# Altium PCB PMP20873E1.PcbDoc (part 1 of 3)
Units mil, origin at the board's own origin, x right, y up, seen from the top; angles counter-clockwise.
Board outline 7700 x 3300 mil, 6 copper layers (Layer 1 - Top Layer, Layer 2 - Inner Signal 1, Layer 3 - Inner Signal 2, Layer 4 - Inner Signal 3, Layer 5 - Inner Signal 4, Layer 6 - Bottom Layer), stack 64 mil thick; 258 components, 121 nets, 676 pads, 168 vias.
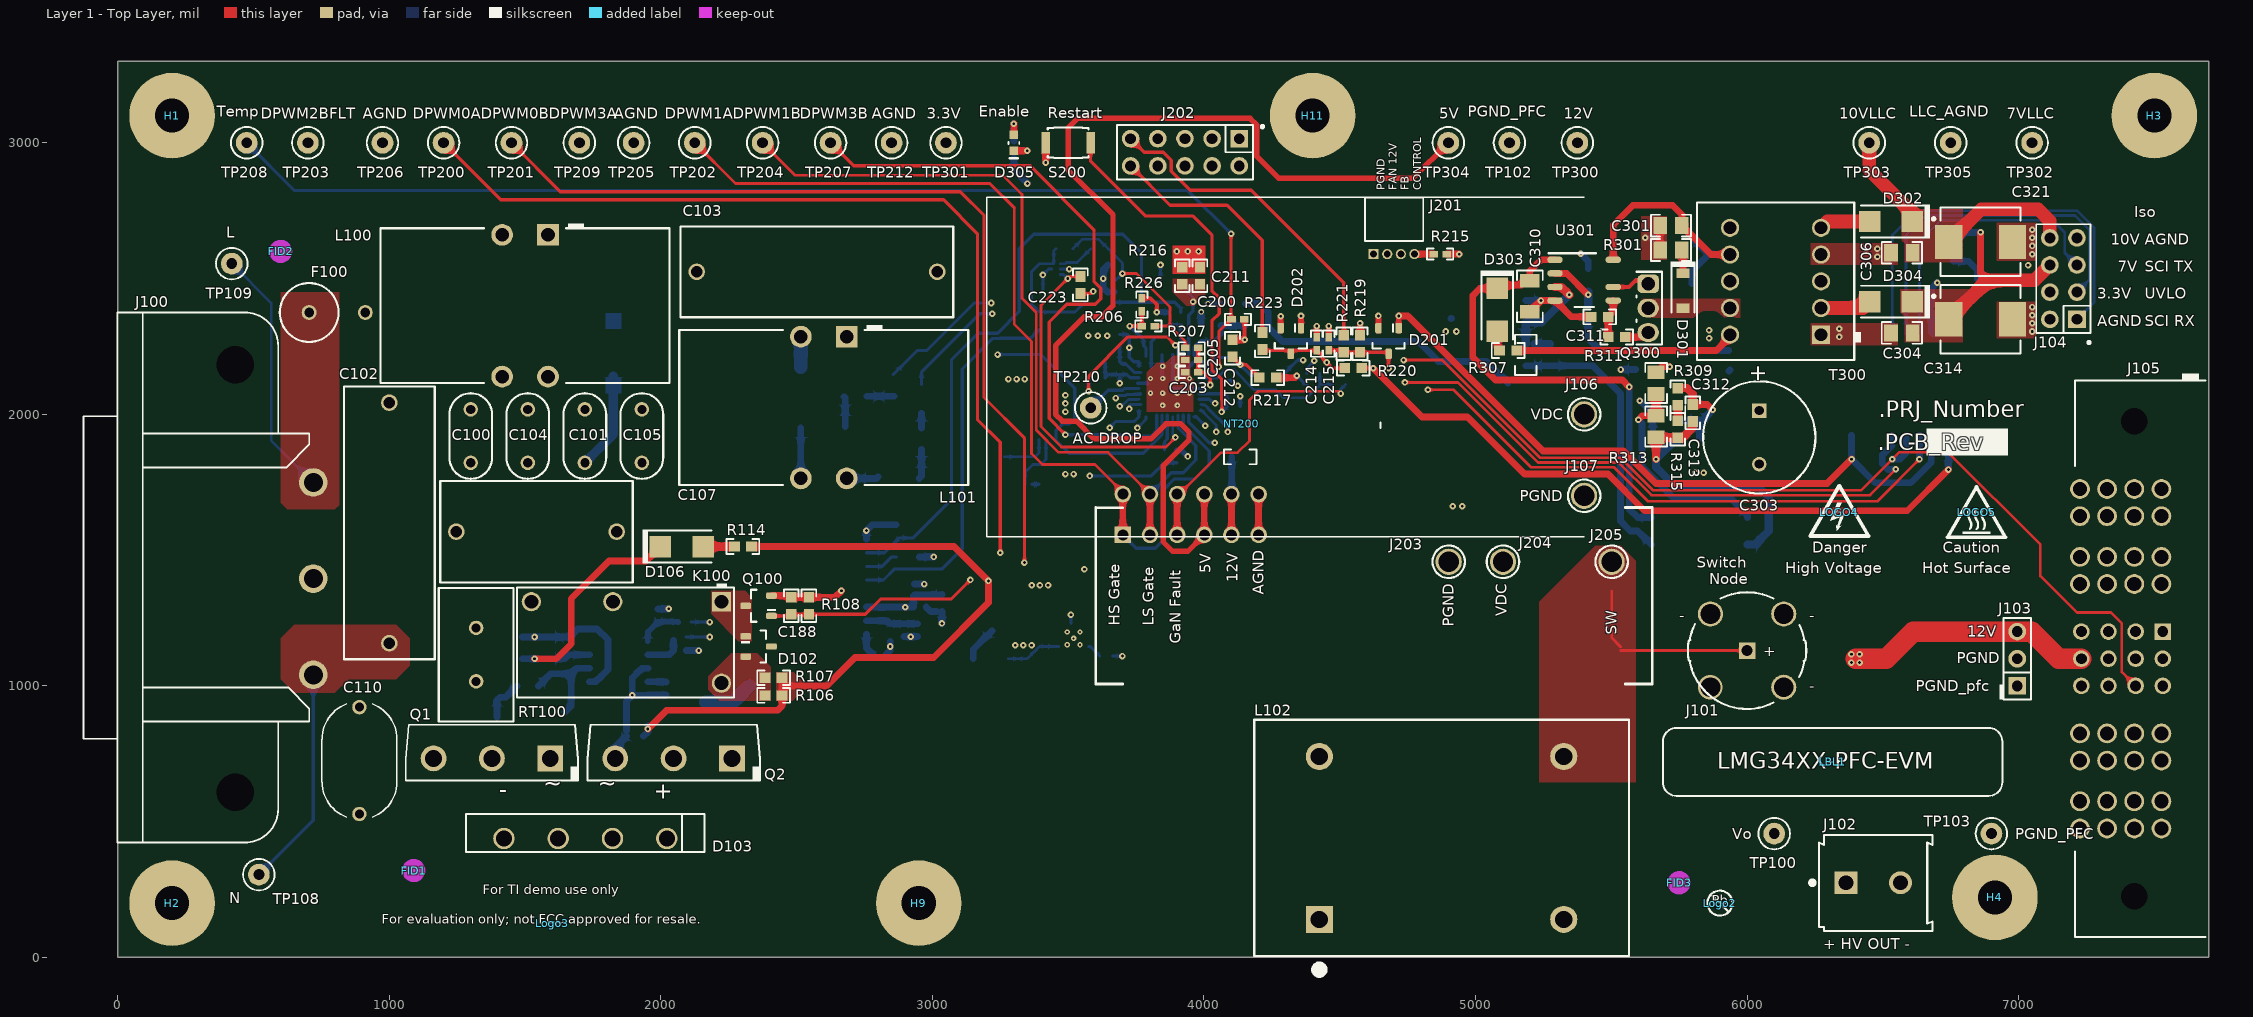
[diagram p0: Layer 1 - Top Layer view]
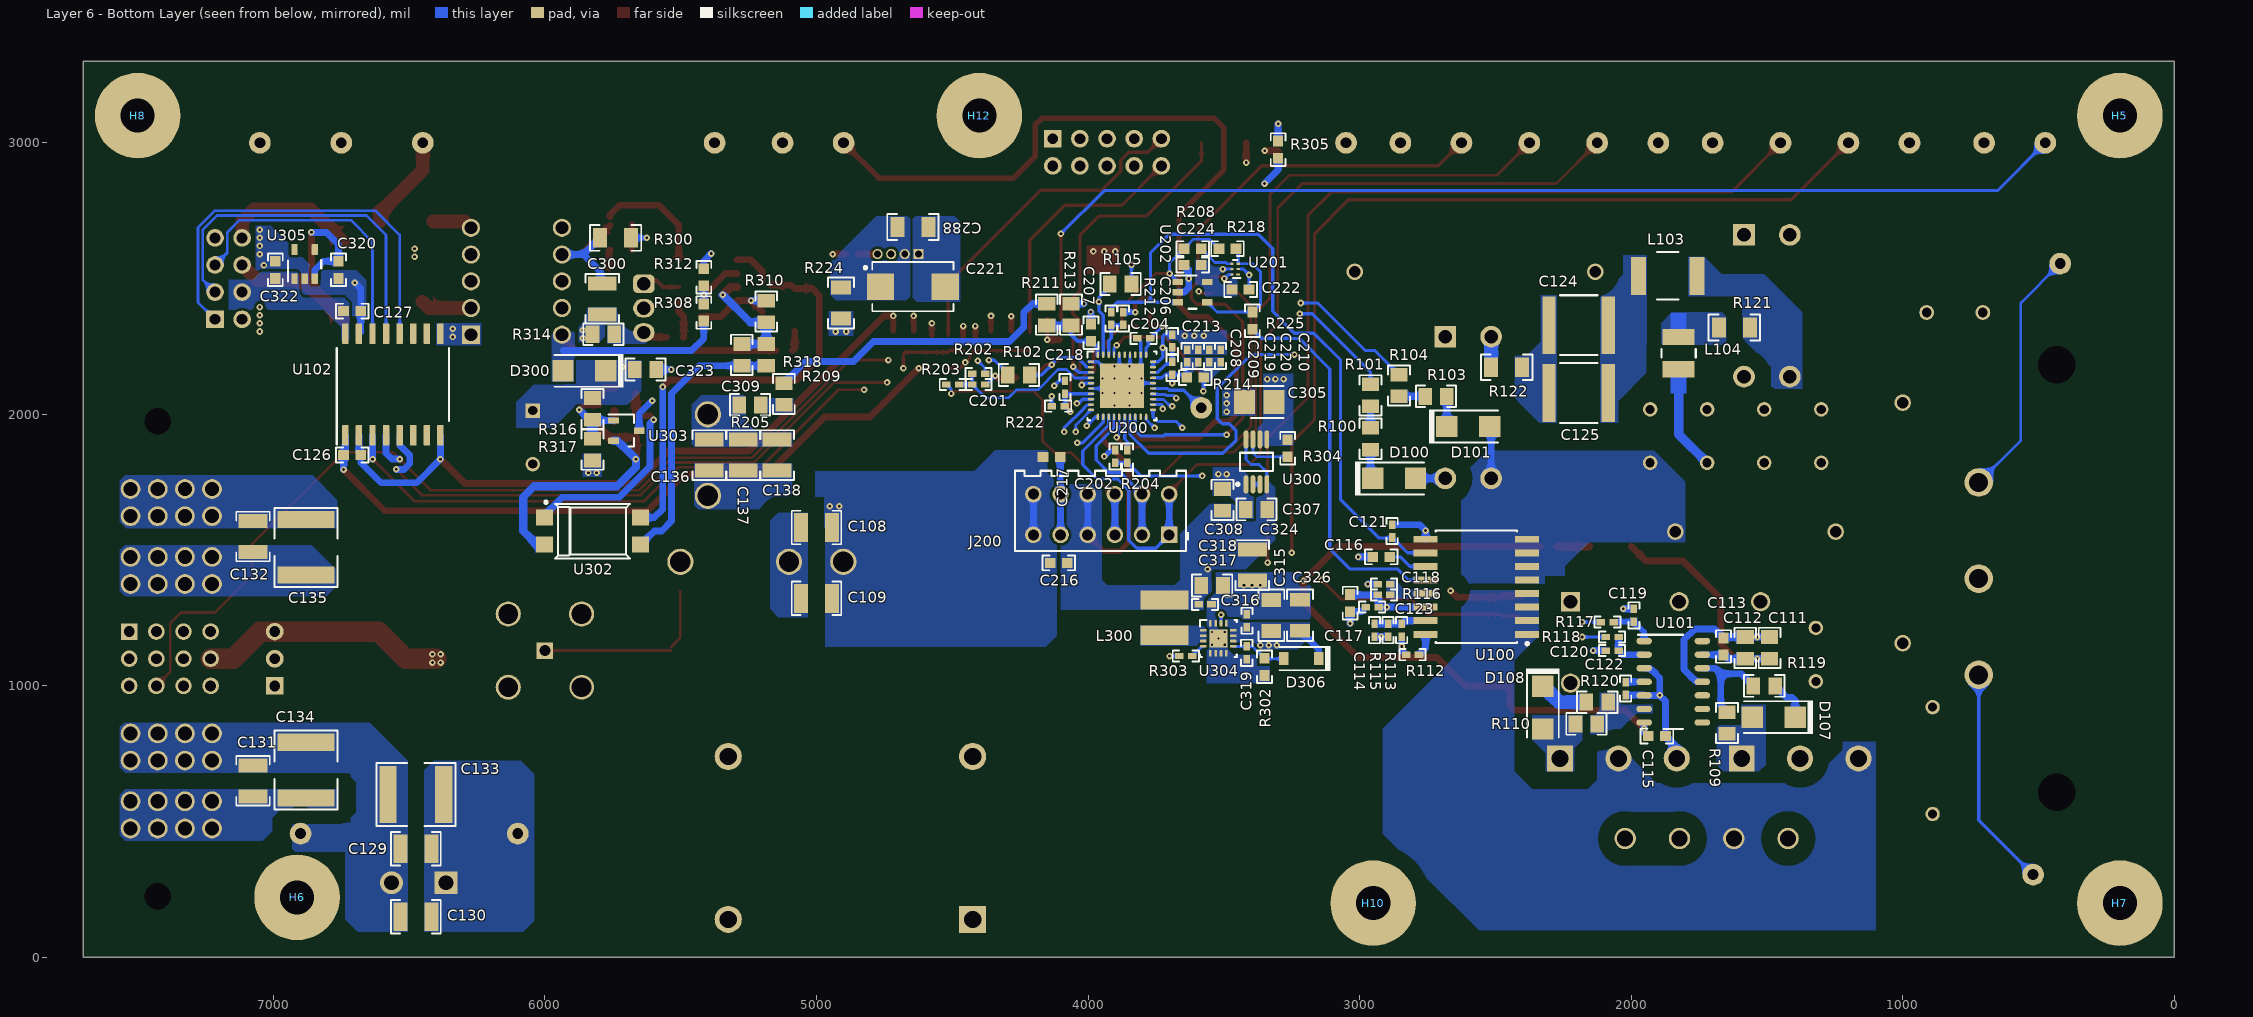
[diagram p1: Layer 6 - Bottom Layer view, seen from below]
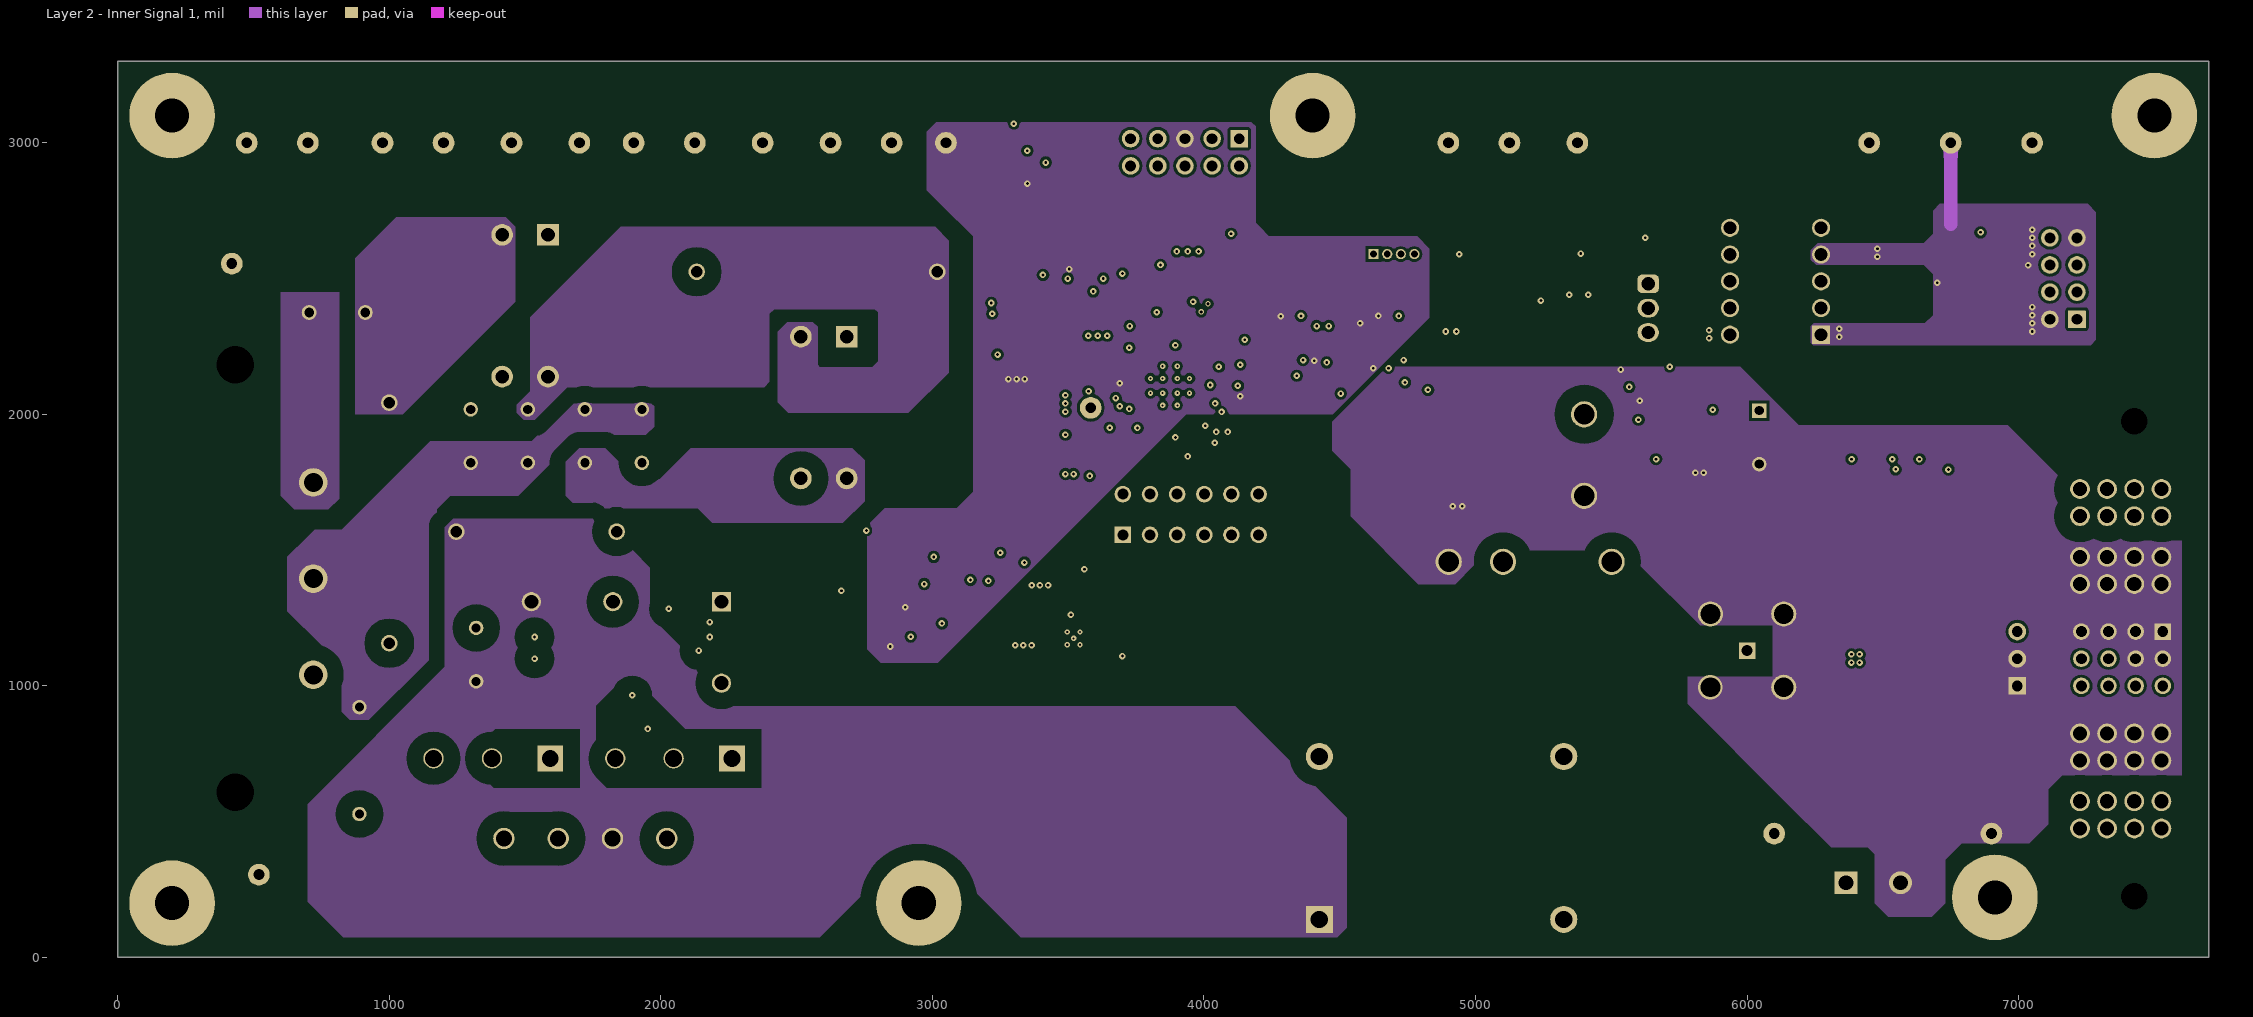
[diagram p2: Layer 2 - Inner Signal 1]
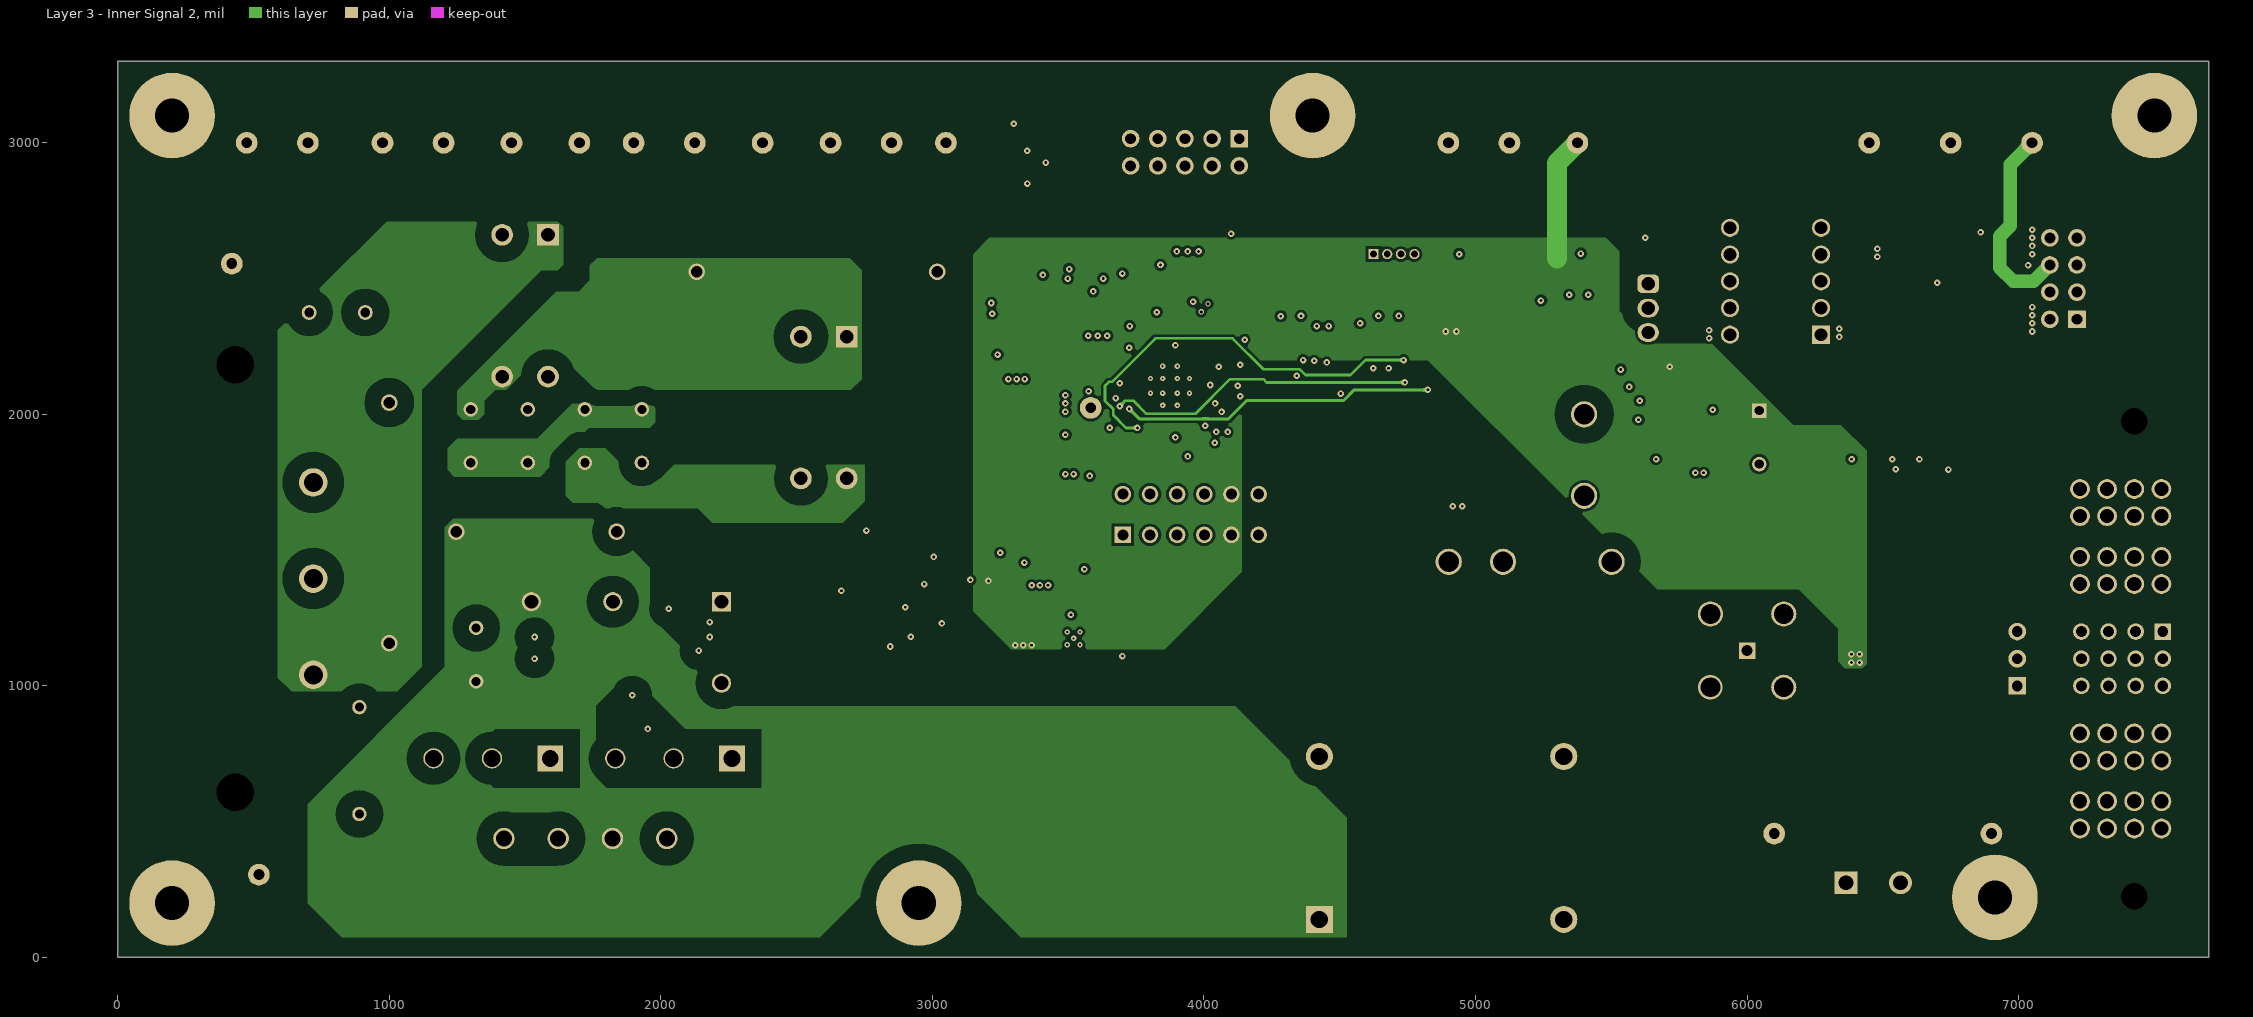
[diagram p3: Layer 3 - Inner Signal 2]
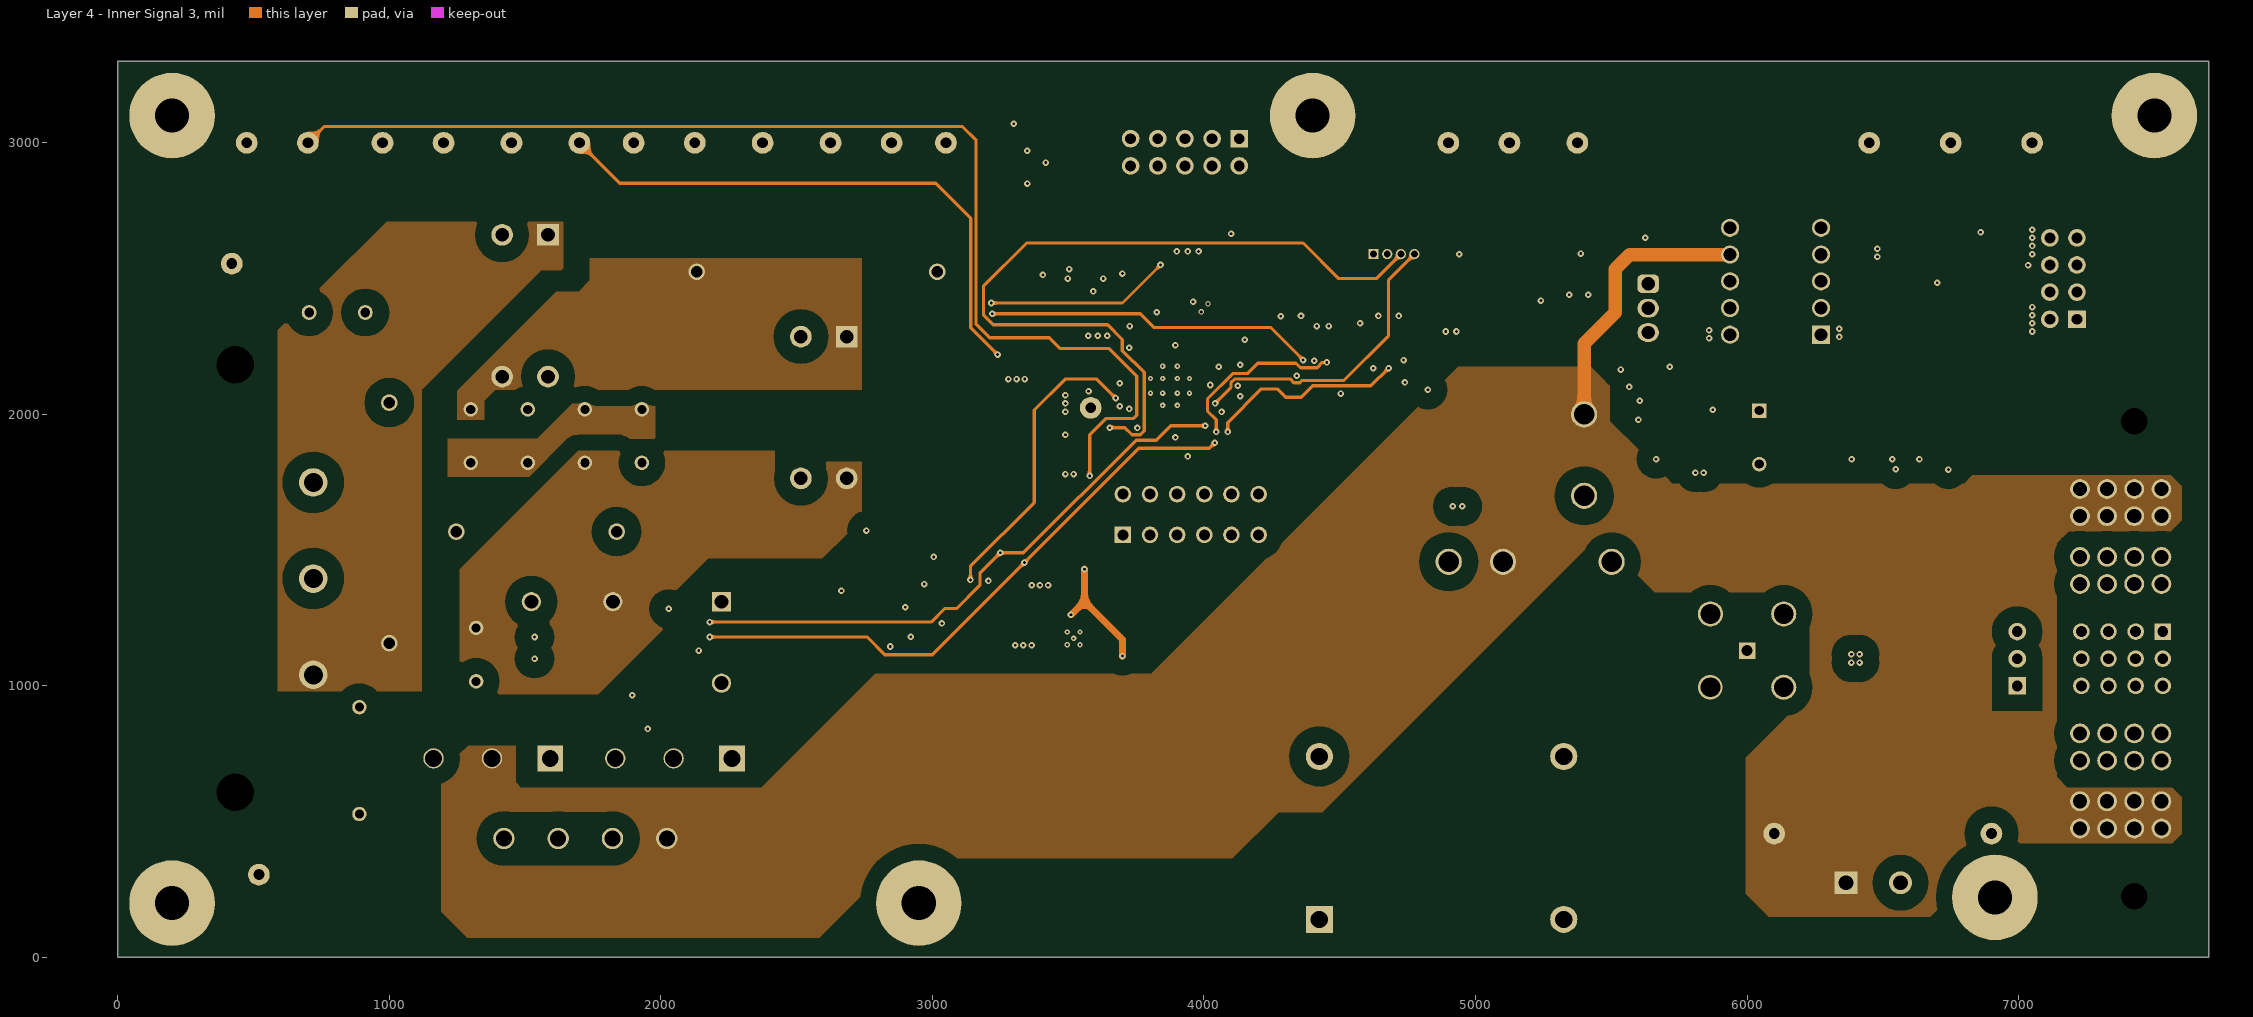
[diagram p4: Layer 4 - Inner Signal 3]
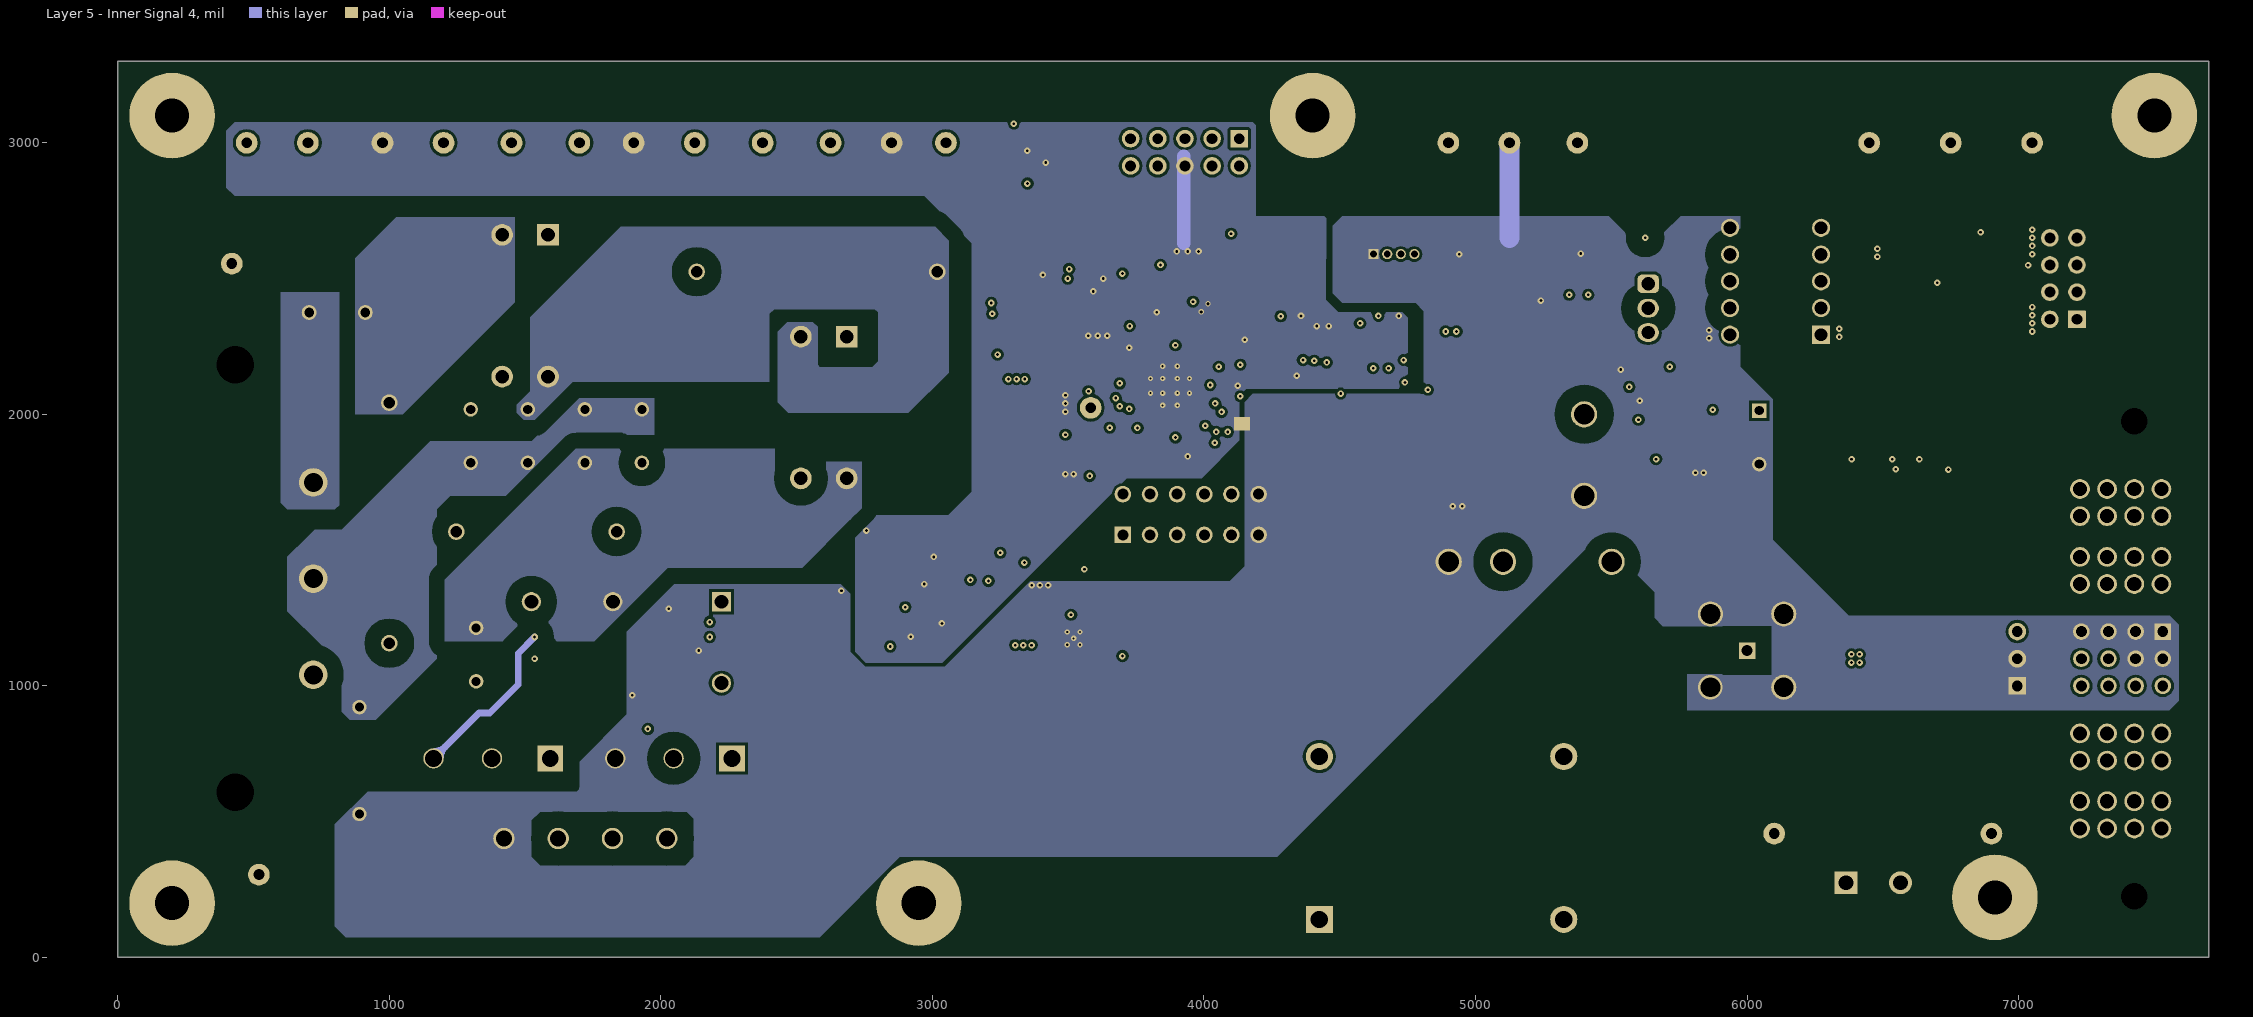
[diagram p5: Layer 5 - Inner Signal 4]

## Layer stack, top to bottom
Top Solder: solder mask 0.4, Solder Resist, Dk 3.5
Layer 1 - Top Layer: signal copper 1.4
Dielectric1: core 10, FR-4 High Tg, Dk 4.8
Layer 2 - Inner Signal 1: signal copper 2.8
Dielectric2: prepreg 10, FR-4 High Tg, Dk 4.8
Layer 3 - Inner Signal 2: signal copper 2.8
Dielectric3: core 10, FR-4 High Tg, Dk 4.8
Layer 4 - Inner Signal 3: signal copper 2.8
Dielectric4: prepreg 10, FR-4 High Tg, Dk 4.8
Layer 5 - Inner Signal 4: signal copper 2.8
Dielectric5: core 10, FR-4 High Tg, Dk 4.8
Layer 6 - Bottom Layer: signal copper 1.4
Bottom Solder: solder mask 0.4, Solder Resist, Dk 3.5

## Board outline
0,0 7700,0 7700,3300 0,3300

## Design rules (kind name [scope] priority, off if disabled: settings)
AcuteAngle [All] p1: minimum=4.50000000000000E+0001 checktracksonly=FALSE
AssemblyTestPointUsage [All] p1: valid=2
Clearance Clearance_5 [InComponent('L104') vs InComponent('L104')] p1: gap=59
Clearance Clearance_4 [InNetClass('VDC_HV') vs OnLayer('M1 Board Outline')] p2: gap=10
Clearance Clearance_SWNode_HV [InNetClass('SWNode') vs not InNetClass('SWNode')] p3: gap=60
Clearance Clearance_EARTH_HV [InNet('EARTH')] p4: gap=60
Clearance Clearance_3 [InNetClass('VAC_NEUTRAL') vs InNet('-BRDG_N')] p5: gap=24
Clearance Clearance_2 [InNetClass('VDC_HV') vs InComponent('Q300')] p6: gap=20
Clearance Clearance_1 [InNetClass('VDC_HV') vs InComponent('T300')] p7: gap=31
Clearance Clearance_VAC_NEUTRAL_HV [InNetClass('VAC_NEUTRAL') vs not InNetClass('VAC_NEUTRAL')] p8: gap=60
Clearance "Clearance_ VAC_LINE_HV" [InNetClass('VAC_LINE') vs not InNetClass('VAC_LINE')] p9: gap=60
Clearance "Clearance_ VAC_LINE_2_HV" [InNetClass('VAC_LINE_2') vs not InNetClass('VAC_LINE_2')] p10: gap=60
Clearance Clearance_SW_L_HV [InNetClass('SW_L') vs not InNetClass('SW_L')] p11: gap=60
Clearance Clearance_VDC_HV_HV [InNetClass('VDC_HV') vs not InNetClass('VDC_HV')and not InComponent('R205')] p12: gap=60
Clearance Clearance_BoardEdge_MountingHoles [OnCopper and InComponentClass('Mounting Holes') vs IsKeepOut] p13: gap=40
Clearance Clearance_BoardEdge_Poly [OnCopper and InPoly vs IsKeepOut] p14: gap=25
Clearance Clearance_BoardEdge [OnCopper and Not InComponentClass('Logo') and not InComponentClass('FiducialMark') and not InRegion(1000,500,4000,800) and Not IsKeepout vs IsKeepOut] p15: gap=75
Clearance Clearance_Poly [InPolygon] p16: gap=10
Clearance [All] p17: gap=7.5
ComponentClearance ComponentClearance_Shunt [InComponentClass('Header') vs InComponentClass('Shunt')] p1 off: gap=0 collisioncheckmode=3 verticalgap=0 showdistances=FALSE
ComponentClearance ComponentClearance_Logo [InComponentClass('Logo')] p2 off: gap=50 collisioncheckmode=3 verticalgap=10 showdistances=FALSE
ComponentClearance ComponentClearance_ScrewToNut [(HasFootprint('NY PMS 440 0025 PH')) vs (HasFootprint('Keystone_1902C'))] p3 off: gap=5 collisioncheckmode=3 verticalgap=10 showdistances=FALSE
ComponentClearance ComponentClearance_MountingHoles [InComponentClass('Mounting Holes')] p4 off: gap=250 collisioncheckmode=3 verticalgap=100000 showdistances=FALSE
ComponentClearance ComponentClearance_SmallPassives [HasFootprint('0201*') or HasFootprint('0402*') or HasFootprint('0508') or HasFootprint('0603*') or HasFootprint('0612') or HasFootprint('0805*') or HasFootprint('0815*') or HasFootprint('0830*') or HasFootprint('1206*') or HasFootprint('1210*') or HasFootprint('1808*') or HasFootprint('1812*') or HasFootprint('1825*') or HasFootprint('2010*') or HasFootprint('2220*') or HasFootprint('2225*') or HasFootprint('2512*') or HasFootprint('2728*') or HasFootprint('3518*') vs HasFootprint('0201*') or HasFootprint('0402*') or HasFootprint('0508') or HasFootprint('0603*') or HasFootprint('0612') or HasFootprint('0805*') or HasFootprint('0815*') or HasFootprint('0830*') or HasFootprint('1206*') or HasFootprint('1210*') or HasFootprint('1808*') or HasFootprint('1812*') or HasFootprint('1825*') or HasFootprint('2010*') or HasFootprint('2220*') or HasFootprint('2225*') or HasFootprint('2512*') or HasFootprint('2728*') or HasFootprint('3518*')] p5 off: gap=20 collisioncheckmode=3 verticalgap=10 showdistances=FALSE
ComponentClearance ComponentClearance_THtoSMT [IsThruComponent vs IsSMTComponent] p6 off: gap=100 collisioncheckmode=3 verticalgap=30 showdistances=FALSE
ComponentClearance ComponentClearance_THtoTH [IsThruComponent vs IsThruComponent] p7 off: gap=118.11 collisioncheckmode=3 verticalgap=30 showdistances=FALSE
ComponentClearance [All] p8 off: gap=40 collisioncheckmode=3 verticalgap=10 showdistances=FALSE
DiffPairsRouting [All] p1: maxlimit=100 minlimit=10 mostfreqgap=10 toplayer_minwidth=15 toplayer_maxwidth=15 toplayer_prefwidth=15 midlayer1_minwidth=15 midlayer1_maxwidth=15 midlayer1_prefwidth=15 midlayer2_minwidth=15 midlayer2_maxwidth=15 midlayer2_prefwidth=15 midlayer3_minwidth=15 midlayer3_maxwidth=15 midlayer3_prefwidth=15 midlayer4_minwidth=15 midlayer4_maxwidth=15 midlayer4_prefwidth=15 bottomlayer_minwidth=15 bottomlayer_maxwidth=15 bottomlayer_prefwidth=15 maxuncoupledlength=1000
FabricationTestPointUsage TestPointUsage [All] p1: valid=2 allowmultiple=FALSE
FabricationTestpoint Testpoint [All] p1: side=3 testpointundercomponent=TRUE minsize=40 maxsize=100 preferedsize=60 minholesize=0 maxholesize=40 preferedholesize=32 testpointgrid=1 allowsidetop=TRUE allowsidebottom=TRUE usegrid=TRUE gridtolerance=0.01
FanoutControl Fanout_LCC [IsLCC] p1: bgadir=Out bgaviamode=Centered fanoutstyle=Auto fanoutdirection=Alternating viagrid=1 // Fanout_LCC (Default Rule)
FanoutControl Fanout_BGA [IsBGA] p2: bgadir=Out bgaviamode=Centered fanoutstyle=Auto fanoutdirection=Alternating viagrid=1 // Fanout_BGA (Default Rule)
FanoutControl Fanout_Default [All] p4: bgadir=Out bgaviamode=Centered fanoutstyle=Auto fanoutdirection=Alternating viagrid=1 // Fanout_Default (Default Rule)
FanoutControl Fanout_Small [(CompPinCount < 5)] p5: bgadir=Out bgaviamode=Centered fanoutstyle=Auto fanoutdirection=OutThenIn viagrid=1 // Fanout_Small (Default Rule)
Height [All] p1: minheight=0 maxheight=2500 prefheight=500
HoleSize [All] p1: absolutevalues=TRUE maxlimit=251 minlimit=7.8 maxpercent=80.000 minpercent=20.000
MinimumAnnularRing MinimumAnnularRing_ThermalPadVias [IsVia and InAnyComponent] p1: minimumring=5.91
MinimumAnnularRing [All] p2: minimumring=3.5
MinimumSolderMaskSliver MinimumSolderMaskSliver_Logo [InComponentClass('Logo') vs InComponentClass('Logo')] p1: minsoldermaskwidth=0.7
MinimumSolderMaskSliver [All] p2: minsoldermaskwidth=0
PlaneConnect [All] p1: planeconnectstyle=Relief reliefexpansion=10 reliefentries=4 reliefconductorwidth=10 reliefairgap=10
PolygonConnect [All] p1: connectstyle=Direct reliefconductorwidth=10 reliefentries=4 polygonreliefangle="90 Angle" airgapwidth=10
RoutingVias ThermalPadVias [IsVia and InAnyComponent] p1: holewidth=7.87 width=19.68 viastyle="Through Hole" minholewidth=7.87 minwidth=19.68 maxholewidth=12.99 maxwidth=23.62
RoutingVias [All] p2: holewidth=12 width=20 viastyle="Through Hole" minholewidth=7.87 minwidth=15 maxholewidth=393.7 maxwidth=314.96
SMDToCorner [All] p1: distance=10000
SilkToSilkClearance [All] p1 off: silktosilkclearance=1
SilkToSolderMaskClearance SilkscreenOverComponentPads [IsPad] p1 off: minsilkscreentomaskgap=1 clearancetoexposedcopper=TRUE
SolderMaskExpansion [All] p1: expansion=1.97
Width [All] p1: maxlimit=100 minlimit=7 preferedwidth=10 checkconnectedcopper=TRUE
15 further rules are at their usual default settings.

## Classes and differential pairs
net class VAC_LINE_2: AC_L
net class LLC: 3V3LLC 7VLLC 10VLLC 12V LLC_AGND NetD302_2 NetD304_2 NetJ104_1 NetJ104_3 NetJ104_5 NetU102_10 NetU102_11 NetU305_4 PGND_PFC
net class VDC_HV: CT1 HVBUS NetC301_2 NetD301_1 NetD301_2
net class VAC_LINE: NetC100_1 NetC101_1 NetC102_1
component class SV601259E2_Power: C100 C101 C102 C103 C104 C105 C107 C108 C109 C110 C111 C112 C113 C114 C115 C116 C117 C118 C119 C120 C121 C122 C123 C124 C125 C126 C127 C129 C130 C131 C132 C133 C134 C135 C136 C137 C138 C188 D100 D101 D102 D103 D106 D107 D108 F100 J100 J101 J102 J103 J104 J105 J106 J107 K100 L100 L101 L102 L103 L104 Q1 Q2 Q100 R100 R101 R102 R103 R104 R105 R106 R107 R108 R109 R110 R112 R113 R114 R115 R116 R117 R118 R119 R120 R121 R122 RT100 TP100 TP102 TP103 TP108 TP109 U100 U101 U102
component class Header: J103 J104 J202
component class SV601259E2_Control: C200 C201 C202 C203 C204 C205 C206 C207 C208 C209 C210 C211 C212 C213 C214 C215 C216 C217 C218 C219 C220 C221 C222 C223 C224 C288 D201 D202 J200 J201 J202 J203 J204 J205 NT200 R202 R203 R204 R205 R206 R207 R208 R209 R211 R212 R213 R214 R215 R216 R217 R218 R219 R220 R221 R222 R223 R224 R225 R226 S200 TP200 TP201 TP202 TP203 TP204 TP205 TP206 TP207 TP208 TP209 TP210 TP212 U200 U201 U202
component class SV601259E2_Bias: C300 C301 C303 C304 C305 C306 C307 C308 C309 C310 C311 C312 C313 C314 C315 C316 C317 C318 C319 C320 C321 C322 C323 C324 C326 D300 D301 D302 D303 D304 D305 D306 L300 Q300 R300 R301 R302 R303 R304 R305 R307 R308 R309 R310 R311 R312 R313 R314 R315 R316 R317 R318 T300 TP300 TP301 TP302 TP303 TP304 TP305 U300 U301 U302 U303 U304 U305
component class "Mounting Holes": H1 H2 H3 H4 H9 H11
component class SV601259E2_Hardware: FID1 FID2 FID3 H1 H2 H3 H4 H5 H6 H7 H8 H9 H10 H11 H12 LBL1 Logo2 Logo3 LOGO4 LOGO5 ZZ1 ZZ2 ZZ3 ZZ4
component class FiducialMark: FID1 FID2 FID3
component class AssemblyNote: ZZ1 ZZ2 ZZ3 ZZ4
component class Label: LBL1
net class SW_L: +BRDG_N -BRDG_N NCD1 NCD2 NCD3 NCD4 NetC111_1 NetD107_1 NetD107_2
net class VAC_NEUTRAL: AC_N NetC102_2 NetC103_2
net class SWNode: SWNODE

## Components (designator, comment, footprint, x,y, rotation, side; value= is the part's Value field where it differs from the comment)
C100 "DE2E3KY222MA2BM01" CAPRD500W60D800H850 1300,1920 r270 top
C101 "DE2E3KY222MA2BM01" CAPRD500W60D800H850 1720,1920 r90 top
C102 "ECQ-U2A474ML" CAPRR2250W80L2550T850H1750 1000,1600 r270 top
C103 "R46KN-4100--P1 M" CAPRR2250W80L2550T850H1750 2575,2525 r0 top
C104 "DE2E3KY222MA2BM01" CAPRD500W60D800H850 1510,1920 r90 top
C105 "DE2E3KY222MA2BM01" CAPRD500W60D800H850 1930,1920 r270 top
C107 "450MPK105J" MPK_1800x950 1542,1568 r0 top
C108 "GRM32DR72J473KW01L" 1210 5000,1583.27 r180 bottom
C109 "GRM32DR72J473KW01L" 1210 5000,1322.05 r180 bottom
C110 "C921U222MYWDBA7317" CAPRD1000W60D900H1200 890,725 r270 top
C111 "0805YD106MAT2A" 0805_HV 1490,1140 r90 bottom
C112 "0805YD106MAT2A" 0805_HV 1580,1140 r90 bottom
C113 "C1608X7R1E105K080AB" 0603 1660,1145 r270 bottom
C114 "GRM155R70J104KA01D" 0402 2945,1205 r270 bottom
C115 "C0603X103K5RACTU" 0603 1905,815 r180 bottom
C116 "C1608X7R1H102K" 0603 2920,1475 r0 bottom
C117 "GRM185R60J105KE26D" 0603 3035,1305 r270 bottom
C118 "GRM155R70J223KA01D" 0402 2910,1375 r180 bottom
C119 "C1005X7R1H102K" 0402 1990,1260 r90 bottom
C120 "GRM155R60J102KA01D" 0402 2070,1130 r0 bottom
C121 "GRM155R60J102KA01D" 0402 2880,1570 r90 bottom
C122 "GRM155R70J104KA01D" 0402 2020,990 r270 bottom
C123 "GRM155R70J104KA01D" 0402 2953.62,1290 r0 bottom
C124 "GA355XR7GB563KW06L" 2220_330_N 2193.41,2328.41 r0 bottom
C125 "GA355XR7GB563KW06L" 2220_330_N 2193.41,2078.41 r0 bottom
C126 "C1608X7R1E105K080AB" 0603 6710,1850 r0 bottom
C127 "C1608X7R1E105K080AB" 0603 6710,2380 r0 bottom
C129 "GRM32DR72J473KW01L" 1210 6475,400 r0 bottom
C130 "GRM32DR72J473KW01L" 1210 6475,150 r0 bottom
C131 "GRM32DR72J473KW01L" 1210 7075,650 r90 bottom
C132 "GRM32DR72J473KW01L" 1210 7075,1550 r270 bottom
C133 "GRM55DR72J224KW01L" 2220 6475,600 r180 bottom
C134 "GRM55DR72J224KW01L" 2220 6880,690 r90 bottom
C135 "GRM55DR72J224KW01L" 2220 6880,1510 r90 bottom
C136 "GRM32DR72J473KW01L" 1210 5395,1850 r270 bottom
C137 "GRM32DR72J473KW01L" 1210 5270,1850 r270 bottom
C138 "GRM32DR72J473KW01L" 1210 5145,1850 r270 bottom
C188 "GRM188R71C102KA01D" 0603 2480,1295 r270 top
C200 "GRM155R60J104KA01D" 0402 4125,2350 r180 top
C201 "GRM155R61A102KA01D" 0402 4403,2110 r180 bottom
C202 "GRM155R70J103KA01D" 0402 3900,1845 r270 bottom
C203 "GRM155R60J104KA01D" 0402 3955,2155 r180 top
C204 "GRM155R60J472KA01D" 0402 3795,2280 r0 bottom
C205 "GRM155R70J103KA01D" 0402 3955,2200 r180 top
C206 "GRM155R60J104KA01D" 0402 3870,2352.72 r270 bottom
C207 "GCM188R71H104KA57D" 0603 3989,2301 r90 bottom
C208 "C1005X5R1A225K050BC" 0402 3690,2170 r90 bottom
C209 "CL05A475MQ5NRNC" 0402 3635,2215 r90 bottom
C210 "CL05A475MQ5NRNC" 0402 3512,2215 r90 bottom
C211 "C1608X7R1H222K" 0603 3985,2510 r90 top
C212 "C1608X7R1H222K" 0603 4105,2243.5 r90 top
C213 "GRM155R61A105KE15D" 0402 3690,2270 r90 bottom
C214 "GRM1555C1H101JA01D" 0402 4415,2260 r90 top
C215 "GRM1555C1H101JA01D" 0402 4460,2260 r90 top
C216 "C1608X7R1E105K080AB" 0603 4108,1453.05 r180 bottom
C217 "C1608X7R1E105K080AB" 0603 4134.09,1843.35 r180 bottom
C218 "C1005X5R1A225K050BC" 0402 4085,2100 r90 bottom
C219 "GRM155R60J104KA01D" 0402 3594,2215 r90 bottom
C220 "GRM155R60J104KA01D" 0402 3553,2215 r90 bottom
C221 "T495X107K016ATE100" 7343-43 4645,2470 r180 bottom
C222 "C1608X7R1E105K080AB" 0603 3438.5,2460 r0 bottom
C223 "GCM188R71H104KA57D" 0603 3544.93,2476.31 r270 top
C224 "C1608X7R1E105K080AB" 0603 3615,2550 r180 bottom
C288 "12063D225KAT2A" 1206 4645,2690 r0 bottom
C300 "GRM32DR72J333KW01L" 1210 5789,2425 r270 bottom
C301 "C2012X7R2E102K" 0805_HV 5720,2695 r180 top
C303 "25ZL330MEFC10X12.5" ZL_1000x1250 6045,1915 r270 top
C304 "GRM21BR71E335KA73L" 0805_HV 6570,2300 r180 top
C305 "293D475X9010B2TE3" 3528-21 3370,2045 r0 bottom
C306 "GRM21BR71E335KA73L" 0805_HV 6570,2595 r180 top
C307 "C0805C106K8PACTU" 0805_HV 3380,1650 r0 bottom
C308 "C0805C106K8PACTU" 0805_HV 3505,1685 r90 bottom
C309 "C0805C473K5RACTU" 0805_HV 5275,2219 r90 bottom
C310 "GRM31CR71E106KA12L" 1206 5200,2435 r270 top
C311 "06035A680JAT2A" 0603 5457,2359 r180 top
C312 "06035A102KAT2A" 0603 5745,2065 r270 top
C313 "C0603C223K3RACTU" 0603 5800,2005 r270 top
C314 "TPSV227K016R0050" 7361-38 6860,2350 r0 top
C315 "1206YD226MAT2A" 1206 3325.16,1259.88 r90 bottom
C316 "C1005X7R1H104K" 0402 3415.16,1239.88 r90 bottom
C317 "C1005X7R1H104K" 0402 3569,1300 r180 bottom
C318 "GRM21BR71A106KE51L" 0805_HV 3543,1369.88 r0 bottom
C319 "GRM155R71E222KA01D" 0402 3415.65,1121.73 r270 bottom
C320 "C1608X7R1E105K080AB" 0603 6760,2532 r90 bottom
C321 "TPSV227K016R0050" 7361-38 6860,2635 r0 top
C322 "C1608X7R1E105K080AB" 0603 6993,2532 r270 bottom
C323 "GRM21BR71E335KA73L" 0805_HV 5630,2165 r180 bottom
C324 "12106D476MAT2A" 1210 3395,1445 r270 bottom
C326 "1206YD226MAT2A" 1206 3220,1260 r90 bottom
D100 "US1K-13-F" SMA 2872.74,1764 r180 bottom
D101 "US1K-13-F" SMA 2600,1955 r180 bottom
D102 "BAT54S-7-F" SOT-23 2360,1145 r0 top
D103 "GBU8J-BP" GBU 1722,438 r180 top
D106 "MURA160T3G" SMA 2077,1513 r0 top
D107 "STPS130A" SMA 1475,885 r0 bottom
D108 "STPS130A" SMA 2325,920 r270 bottom
D201 "BAT54S-7-F" SOT-23 4680,2270 r270 top
D202 "BAT54S-7-F" SOT-23 4320,2270 r270 top
D300 "SS110-TP" SMA 5855,2160 r0 bottom
D301 "CGRM4007-G" SOD-123 5764,2455 r270 top
D302 "SS110-TP" SMA 6530,2710 r180 top
D303 "ES1D-13-F" SMA 5080,2385 r270 top
D304 "SS110-TP" SMA 6530,2415 r180 top
D305 "LG L29K-G2J1-24-Z" "LG L29K_GREEN" 3300,3000 r270 top
D306 "MMSZ4696T1G" SOD-123 3215,1100 r0 bottom
F100 "0217015.MXEP" Fuse_217_015_Verical 705,2375 r180 top
FID1 "Fiducial" Fiducial10-20 1090,320 r0 top
FID2 "Fiducial" Fiducial10-20 600,2600 r0 top
FID3 "Fiducial" Fiducial10-20 5750,275 r0 top
H1 "NY PMS 440 0025 PH" "NY PMS 440 0025 PH" 200,3100 r90 top
H2 "NY PMS 440 0025 PH" "NY PMS 440 0025 PH" 200,200 r90 top
H3 "NY PMS 440 0025 PH" "NY PMS 440 0025 PH" 7500,3100 r180 top
H4 "NY PMS 440 0025 PH" "NY PMS 440 0025 PH" 6913,221 r90 top
H5 "1902C" Keystone_1902C 200,3100 r180 bottom
H6 "1902C" Keystone_1902C 6913,221 r180 bottom
H7 "1902C" Keystone_1902C 200,200 r180 bottom
H8 "1902C" Keystone_1902C 7500,3100 r270 bottom
H9 "NY PMS 440 0025 PH" "NY PMS 440 0025 PH" 2950,200 r90 top
H10 "1902C" Keystone_1902C 2950,200 r180 bottom
H11 "NY PMS 440 0025 PH" "NY PMS 440 0025 PH" 4400,3100 r90 top
H12 "1902C" Keystone_1902C 4400,3100 r180 bottom
J100 "703W-00/54" CONN_QUALTEK-703W-0054 325,1395 r90 top
J101 "BNC5-J-P-GN-ST-TH2D" Samtec_BNC5-J-P-GN-ST-TH2D 6000,1130 r180 top
J102 "282841-2" TEC_282841-2 6465,275 r0 top
J103 "TSW-103-07-G-S" TSW-103-07-G-S 6995,1100 r90 top
J104 "TSW-104-07-G-D" TSW-104-07-G-D 7165,2500 r90 top
J105 "PESC-02-12-02-01-L-RA-LC" Samtec_PESC-02-12-02-01-x-RA-LC 7700,1100 r270 top
J106 "VDC" Mill-Max_0312-0-15-15-34-27-10-0 5400,2000 r270 top
J107 "PGND" Mill-Max_0312-0-15-15-34-27-10-0 5400,1700 r270 top
J200 "0448120024" Molex_0448120024 3951.3,1631.05 r0 bottom
J201 "851-43-004-20-001000" CONN_851-43-004-20-001000 4700,2590 r180 top
J202 "TSW-105-07-G-D" TSW-105-07-G-D 3930,2965 r180 top
J203 "Suggest using a net name here" Mill-Max_0312-0-15-15-34-27-10-0 4901.3,1457.04 r90 top
J204 "Suggest using a net name here" Mill-Max_0312-0-15-15-34-27-10-0 5101.3,1457.05 r90 top
J205 "Suggest using a net name here" Mill-Max_0312-0-15-15-34-27-10-0 5501.3,1457.04 r90 top
K100 "G5Q-1A4 DC12" Relay_G5Q-1A4 1870,1160 r270 top
L100 "7840-21-0021" 7840-21-0021 1500,2400 r270 top
L101 "7840-21-0021" 7840-21-0021 2600,2025 r270 top
L102 "7840-09-0014" IND_7840-09-0014 4875,440 r90 top
L103 "ASPI-0403S-103M-T" ASPI-0403S 1865,2510 r180 bottom
L104 "LQH43MN152K03L" LQH43M 1825,2225 r270 bottom
L300 "SDR0403-2R2ML" SDR0403 3719,1251 r90 bottom
LBL1 "Size: 1.25\" x 0.25\"" Label_1250x250 6315,720 r0 top
Logo2 "Pb-Free Symbol" Pb-Free_Overlay_Small 5900,200 r0 top
Logo3 "FCC disclaimer" FCC_disclaimer 1600,125 r0 top
LOGO4 "DANGER HIGH VOLTAGE" IEC_HighVoltage_Small 6340,1640 r0 top
LOGO5 "CAUTION HOT SURFACE" IEC_HotSurface_Small 6845,1640 r0 top
NT200 "Net-Tie" Net-Tie_50milWide_30milLong 4140,1965 r180 top net-tie
Q1 "STY105NM50N" TO-247 1378,733 r180 top
Q2 "STY105NM50N" TO-247 2047,733 r180 top
Q100 "2N7002ET1G" SOT-23 2360,1295 r180 top
Q300 "STD3NK80Z-1" IPAK 5636,2391 r270 top
R100 "RT0805BRD07348KL" 0805_HV 2960,1910 r270 bottom
R101 "RT0805BRD07348KL" 0805_HV 2960,2070 r270 bottom
R102 "RT0805BRD07348KL" 0805_HV 4255,2145 r0 bottom
R103 "RT0805BRD07348KL" 0805_HV 2718.74,2066.26 r180 bottom
R104 "RT0805BRD07348KL" 0805_HV 2855,2106.26 r270 bottom
R105 "RT0805BRD07348KL" 0805_HV 3880,2480 r180 bottom
R106 "CRCW060351R1FKEA" 0603 2415,965 r0 top
R107 "CRCW060351R1FKEA" 0603 2415,1030 r0 top
R108 "RC0603FR-0710KL" 0603 2545,1295 r90 top
R109 "ERJ-6ENF4991V" 0805_HV 1647,863 r90 bottom
R110 "ERJ-6ENF4991V" 0805_HV 2165,860 r180 bottom
R112 "CRCW040210K0FKED" 0402 2805,1115 r0 bottom
R113 "CRCW040212K7FKED" 0402 2845,1205 r270 bottom
R114 "CRCW0603200RFKEA" 0603 2302.5,1513 r0 top
R115 "CRCW04025K49FKED" 0402 2895,1205 r90 bottom
R116 "CRCW0402330KJNED" 0402 2910,1335 r180 bottom
R117 "CRCW04021K00JNED" 0402 2087.62,1235 r0 bottom
R118 "CRCW04021K00JNED" 0402 2070,1180 r0 bottom
R119 "CRCW080510R0FKEA" 0805_HV 1510,1000 r0 bottom
R120 "CRCW080510R0FKEA" 0805_HV 2125,940 r180 bottom
R121 "CRCW12062K00FKEA" 1206 1620,2320 r0 bottom
R122 "CRCW1206100RFKEA" 1206 2458.41,2173.41 r180 bottom
R202 "ERJ-2RKF1002X" 0402 4403,2150 r180 bottom
R203 "CRCW04022K00JNED" 0402 4498,2110 r0 bottom
R204 "CRCW04023K30JNED" 0402 3855,1845 r270 bottom
R205 "RT0805BRD07348KL" 0805_HV 5245,2035 r0 bottom
R206 "ERA-2AEB3091X" 0402 3795,2325 r180 top
R207 "CRCW04021K40FKED" 0402 3955,2245 r180 top
R208 "CRCW06032K00JNEA" 0603 3615,2610 r180 bottom
R209 "RT0805BRD07348KL" 0805_HV 5120,2075 r270 bottom
R211 "RT0805BRD07348KL" 0805_HV 4152,2367 r90 bottom
R212 "CRCW040210K0JNED" 0402 3915,2352.72 r90 bottom
R213 "RT0805BRD075K11L" 0805_HV 4063,2367 r270 bottom
R214 "CRCW06031R00FKEA" 0603 3605,2135 r0 bottom
R215 "CRCW040210K0JNED" 0402 4870,2590 r180 top
R216 "RT0603BRD075K11L" 0603 3920,2510 r270 top
R217 "RT0603BRD075K11L" 0603 4235,2135 r180 top
R218 "CRCW06032K00JNEA" 0603 3486.5,2610 r180 bottom
R219 "CRCW06032K00JNEA" 0603 4575,2260 r90 top
R220 "CRCW06032K00JNEA" 0603 4550,2170 r0 top
R221 "CRCW0603100RJNEA" 0603 4515,2260 r90 top
R222 "CRCW0402221RFKED" 0402 4110,2030 r0 bottom
R223 "CRCW0603100RJNEA" 0603 4215,2270 r90 top
R224 "ERJ-8ENF10R0V" 1206 4910,2410 r270 bottom
R225 "RC0603FR-071KL" 0603 3395,2345 r90 bottom
R226 "ERA-2AEB4871X" 0402 3771.38,2403.62 r270 top
R300 "RC1206FR-07300KL" 1206 5740,2650 r0 bottom
R301 "ERJ-6GEYJ201V" 0805_HV 5720,2605 r180 top
R302 "CRCW06032K00JNEA" 0603 3350,1070 r270 bottom
R303 "CRCW0402100KFKED" 0402 3640,1110 r0 bottom
R304 "RG1608P-334-B-T5" 0603 3265,1875 r90 bottom
R305 "RT0603DRE07750RL" 0603 3300,2975 r270 bottom
R307 "RC0603FR-0720RL" 0603 5120,2235 r0 top
R308 "CRCW060360K4FKEA" 0603 5415,2375 r270 bottom
R309 "CRCW08053K01FKEA" 0805_HV 5665,2115 r90 top
R310 "CRCW080522K1FKEA" 0805_HV 5185,2379 r270 bottom
R311 "CRCW06031K00FKEA" 0603 5519.99,2285.01 r0 top
R312 "CRCW060321K5FKEA" 0603 5415,2505 r270 bottom
R313 "CRCW08052K00FKEA" 0805_HV 5665,1955 r90 top
R314 "CRM0805-FX-R910ELF" 0805_HV 5785,2295 r180 bottom
R315 "CRCW06031K00FKEA" 0603 5745,1945 r90 top
R316 "CRCW080512K1FKEA" 0805_HV 5825,2020 r90 bottom
R317 "CRCW08051K24FKEA" 0805_HV 5825,1870 r90 bottom
R318 "ERJ-6ENF1963V" 0805_HV 5185,2219 r270 bottom
RT100 "B59751B0120A070" TDK_B751 1320,1115 r0 top
S200 "SKRKAEE010" SW_SKRKAEE010 3500,3000 r180 top
T300 "750315894" Wurth_750315894 6105,2490 r180 top
TP100 "Vo" KEYSTONE5000 6100,456 r180 top
TP102 "PGND_PFC" KEYSTONE5001 5125,3000 r0 top
TP103 "PGND_PFC" KEYSTONE5001 6900,456 r180 top
TP108 "N" KEYSTONE5001 519.76,304.76 r0 top
TP109 "L" KEYSTONE5000 420,2555 r0 top
TP200 "DPWM0A" Keystone5002 1200,3000 r180 top
TP201 "DPWM0B" Keystone5002 1450,3000 r180 top
TP202 "DPWM1A" Keystone5002 2125,3000 r180 top
TP203 "DPWM2BFLT" Keystone5002 700,3000 r180 top
TP204 "DPWM1B" Keystone5002 2375,3000 r180 top
TP205 "AGND" Keystone5001 1900,3000 r180 top
TP206 "AGND" Keystone5001 975,3000 r180 top
TP207 "DPWM3B" Keystone5002 2625,3000 r180 top
TP208 "Temp" Keystone5002 475,3000 r180 top
TP209 "DPWM3A" Keystone5002 1700,3000 r90 top
TP210 "AC DROP" Keystone5002 3583,2024 r90 top
TP212 "AGND" KEYSTONE5001 2850,3000 r180 top
TP300 "12V" KEYSTONE5000 5375,3000 r180 top
TP301 "3.3V" KEYSTONE5000 3050,3000 r180 top
TP302 "7VLLC" Keystone5000 7050,3000 r180 top
TP303 "10VLLC" Keystone5000 6450,3000 r180 top
TP304 "5V" Keystone5000 4900,3000 r180 top
TP305 "LLC_AGND" Keystone5001 6750,3000 r180 top
U100 "ACS716KLATR-12CB-NL-T" SOIC-16 2570,1365 r0 bottom
U101 "UCC27714D" D0014A_N 1845,1015 r180 bottom
U102 "ISO7831FDWR" DW0016B_N 6560,2110 r90 bottom
U200 "UCD3138RHAR" RHA0040B 3875,2105 r180 bottom
U201 "SN74LVC1G3157DRYR" DRY0006A 3458.5,2534.93 r0 bottom
U202 "OPA376AIDBVT" DBV0005A_N 3615,2450 r180 bottom
U300 "LP2986AIMM-3.3" MUA08A_N 3380,1825 r90 bottom
U301 "UCC28740DR" D0007A_N 5400,2494 r0 top
U302 "LTV-817S" DIP254P762X350-4 5825,1570 r180 bottom
U303 "TLV431ACDBZR" DBZ0003A_N 5700,1940 r180 bottom
U304 "TPS62153RGTT" RGT0016C 3520.16,1174.88 r180 bottom
U305 "TLV70133DBVT" DBV0005A_N 6885,2553 r90 bottom
ZZ1 "This Assembly Note is for PCB labels only" AssemblyNoteLabel 3400,4400 r0 top
ZZ2 "These assemblies are ESD sensitive, ESD precautions shall be observed." AssemblyNote 3400,4200 r0 top
ZZ3 "These assemblies must be clean and free from flux and all contaminants. Use of no clean flux is not acceptable." AssemblyNote 3400,4000 r0 top
ZZ4 "These assemblies must comply with workmanship standards IPC-A-610 Class 2, unless otherwise specified." AssemblyNote 3400,3800 r0 top

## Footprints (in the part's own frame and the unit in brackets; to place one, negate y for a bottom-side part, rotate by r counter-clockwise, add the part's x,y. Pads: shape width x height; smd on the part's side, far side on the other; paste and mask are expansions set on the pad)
0402 [mm] "0402 from SM-752 data"
  rect 0.8x0.6 smd: 1(-0.6,0) 2(0.6,0)
  silkscreen extent -1.22,-0.52 1.22,0.52, body extent -0.55,-0.3 0.55,0.3, height 0.6
0603 [mm] "0603 from SM-752 data"
  rect 1x0.95 smd: 1(-0.8,0) 2(0.8,0)
  silkscreen extent -1.52,-0.69 1.52,0.69, body extent -0.87,-0.47 0.87,0.47, height 1
0805_HV [mil] "0805 with 30mil clearance between pads"
  rect 50x63 smd: 1(-40,0) 2(40,0)
  silkscreen extent -74,-40 74,40, body extent -43,-29 43,29, height 57
1206 [mm] "1206 from SM-752 data"
  rect 1.3x1.85 smd: 1(-1.45,0) 2(1.45,0)
  silkscreen extent -2.4,-1.21 2.4,1.21, body extent -1.7,-0.9 1.7,0.9, height 1.35
1210 [mm] "1210 from SM-752 data"
  rect 1.3x2.7 smd: 1(-1.45,0) 2(1.45,0)
  silkscreen extent -2.32,-1.57 2.32,1.57, body extent -1.7,-1.35 1.7,1.35, height 1.35
2220 [mm] "Chip Capacitor, Body 5.7x5.0mm, IPC Medium Density"
  rect 1.6x5.3 smd: 1(-2.6,0) 2(2.6,0)
  silkscreen extent -3.69,-2.94 3.69,2.94, body extent -2.95,-2.62 2.95,2.62, height 1.35
2220_330_N [mm] "Chip Capacitor, 2-Leads, Body 5.70x5.00mm, IPC Medium Density"
  rect 1.25x5.4 smd: 1(-2.775,0) 2(2.775,0)
  silkscreen extent -1.78,-2.8 1.75,2.8, body extent -3.05,-2.7 3.05,2.7, height 3.3
3528-21 [mm] "Medium Density IPC, based on SM-782 section 8.4"
  rect 1.95x2.25 smd: 1(-1.375,0) 2(1.375,0)
  silkscreen extent -2.29,-1.5 0.76,1.5, body extent -1.85,-1.5 1.85,1.5, height 2.1
7343-43 [mm] "Medium density IPC based on Kemet T495 series"
  rect 2.55x2.45 smd: 1(-3.025,0) 2(3.025,0)
  silkscreen extent -4.56,-2.3 3.8,2.3, body extent -3.8,-2.3 3.8,2.3, height 4.3
7361-38 [mm] "Medium density IPC based on AVX dimensions for TPS series"
  rect 2.55x3.2 smd: 1(-2.975,0) 2(2.975,0)
  silkscreen extent -4.51,-3.2 3.75,3.2, body extent -3.75,-3.15 3.75,3.15, height 3.8
7840-21-0021 [mil] "TH, 4-Leads, Dia 1064mil"
  rect 80x80 hole 50: 1(-261,84.5)
  round 80 hole 50: 2(-261,-84.5) 3(261,-84.5) 4(261,84.5)
  silkscreen extent -303,-532 285,532, body extent -281,-532 281,532, height 1064
ASPI-0403S [mm] "SMD, 2-Leads, Body 6.6X4.45mm"
  rect 1.4x3.56 smd: 1(-2.73,0) 2(2.73,0)
  silkscreen extent -1,-2.22 1,2.22, body extent -3.3,-2.23 3.3,2.23, height 2.92
AssemblyNote [mil] "Assembly Note"
AssemblyNoteLabel [mil] "Assembly Note for PCB Labels"
CAPRD500W60D800H850 [mm] "RADIAL CAPACITOR"
  round 1.35 hole 0.85: 1(-2.5,0) 2(2.5,0)
  silkscreen extent -4,-2 4,2, body extent -3.97,-2.5 4,2.5, height 10.99
CAPRD1000W60D900H1200 [mm] "Disk, Radial Capacitor"
  round 1.35 hole 0.85: 1(-5,0) 2(5,0)
  silkscreen extent -5.3,-3.5 5.3,3.5, body extent -4.48,-3.5 4.48,3.5, height 11.99
CAPRR2250W80L2550T850H1750 [mm] "PANASONIC"
  round 1.55 hole 1.05: 1(-11.25,0) 2(11.25,0)
  silkscreen extent -12.75,-4.25 12.75,4.25, body extent -12.75,-4.25 12.75,4.25, height 17.5
CONN_851-43-004-20-001000 [mm] "MILL-MAX"
  rect 0.95x0.95 hole 0.65: 1(1.905,0)
  round 0.95 hole 0.65: 2(0.635,0) 3(-0.635,0) 4(-1.905,0)
  silkscreen extent -2.73,-5.31 2.73,-1.22, body extent -2.73,-5.31 2.73,0.23, height 2.23
CONN_QUALTEK-703W-0054 [mil] "AC Receptacle"
  round 105 hole 70: 1(354.33,-395) 2(-354.33,-395) 3(0,-395)
  round 39.37 hole 137.8 unplated: MH1(-787.4,-107.36) MH2(787.4,-107.36)
  silkscreen extent -972,-380 981,452, body extent -972,-477 981,452, height 1130
D0007A_N [mm] "SOIC, 7-Leads, Body 4.9x3.9mm, Pitch 1.27mm, IPC Medium Density"
  oval 1.45x0.6 smd: 1(-2.725,1.905) 2(-2.725,0.635) 3(-2.725,-0.635) 4(-2.725,-1.905) 5(2.725,-1.905) 6(2.725,-0.635) 8(2.725,1.905)
  silkscreen extent -3.32,-2.5 1.1,2.52, body extent -3.01,-2.45 3.01,2.45, height 1.75
D0014A_N [mm] "SOIC, 14-Leads, Body 8.7x3.9mm, Pitch 1.27mm, IPC Medium Density"
  oval 1.45x0.6 smd: 1(-2.725,3.81) 2(-2.725,2.54) 3(-2.725,1.27) 4(-2.725,0) 5(-2.725,-1.27) 6(-2.725,-2.54) 7(-2.725,-3.81) 8(2.725,-3.81) 9(2.725,-2.54) 10(2.725,-1.27) 11(2.725,0) 12(2.725,1.27) 13(2.725,2.54) 14(2.725,3.81)
  silkscreen extent -3.3,-4.4 0.9,4.4, body extent -3.02,-4.32 3.02,4.32, height 1.6
DBV0005A_N [mm] "SOT23, 5-Leads, Body 2.9x1.6mm, Pitch 0.95mm, Lead Span 2.8mm, IPC Medium Density"
  rrect17% 1x0.6 smd: 1(-1.375,0.95) 2(-1.375,0) 3(-1.375,-0.95) 4(1.375,-0.95) 5(1.375,0.95)
  silkscreen extent -1.63,-1.55 0.38,1.55, body extent -1.42,-1.46 1.42,1.46, height 1.09
DBZ0003A_N [mm] "SOT23, 3-Leads, Body 2.9x1.3mm, Pitch 0.95mm, Lead Span 2.4mm, IPC Medium Density"
  rrect17% 1x0.6 smd: 1(-1.2,0.95) 2(-1.2,-0.95) 3(1.2,0)
  silkscreen extent -1.65,-1.5 0.7,1.5, body extent -1.26,-1.46 1.26,1.46, height 0.98
DIP254P762X350-4 [mm] "LITE-ON"
  rect 1.6x1.5 smd: 1(-4.5,1.27) 2(-4.5,-1.27) 3(4.5,-1.27) 4(4.5,1.27)
  silkscreen extent -4.47,-2.55 3.5,2.82, body extent -5.23,-2.55 5.23,2.55, height 4.62
DRY0006A [mm] "PSON, 6-Leads, Body 1x1.45mm, Pitch 0.5mm, TI Recommended"
  rect 0.35x0.2 smd: 1(-0.275,0.5)
  rect 0.3x0.2 smd: 2(-0.3,0) 3(-0.3,-0.5) 4(0.3,-0.5) 5(0.3,0) 6(0.3,0.5)
  silkscreen extent -0.5,-0.85 0.2,0.85, body extent -0.53,-0.75 0.53,0.75, height 0.61
DW0016B_N [mm] "SOIC, 16-Leads, Body 10.5x7.6mm, Pitch 1.27mm, IPC Medium Density"
  rrect17% 1.9x0.6 smd: 1(-4.75,4.445) 2(-4.75,3.175) 3(-4.75,1.905) 4(-4.75,0.635) 5(-4.75,-0.635) 6(-4.75,-1.905) 7(-4.75,-3.175) 8(-4.75,-4.445) 9(4.75,-4.445) 10(4.75,-3.175) 11(4.75,-1.905) 12(4.75,-0.635) 13(4.75,0.635) 14(4.75,1.905) 15(4.75,3.175) 16(4.75,4.445)
  silkscreen extent -5.6,-5.25 3.4,5.25, body extent -5.17,-5.15 5.17,5.15, height 2.59
FCC_disclaimer [mil]
Fiducial10-20 [mm]
  round 1 smd mask+0.5: 1(0,0)
  Layer 1 - Top Layer keep-out circle w1.178: c0,0 r0.5
Fuse_217_015_Verical [mm] "TH, 2-Leads, Dia 5.5mm, Vertical, Pin Spacing 5.25mm"
  round 1.4 hole 0.9: 1(0,0) 2(-5.25,0)
  silkscreen extent -2.75,-2.75 2.75,2.75, body extent -5.57,-2.74 2.75,2.75, height 23.82
GBU [mm] "Comchip / Diodes Inc diode bridge"
  round 2 hole 1.5: 1(-7.62,0) 2(-2.54,0) 3(2.54,0) 4(7.62,0)
  silkscreen extent -11.15,-2.28 11.15,1.28, body extent -11.15,-2.28 11.15,1.28, height 21.55
IEC_HighVoltage_Small [mil]
  silkscreen extent -107,-88 107,97
IEC_HotSurface_Small [mil]
  silkscreen extent -107,-93 107,92
IND_7840-09-0014 [mil] "NOVA MAGNETICS"
  rrect4% 100x100 hole 63.5: 1(-300,450)
  round 100 hole 63.5: 2(300,450) 3(300,-450) 4(-300,-450)
  silkscreen extent -500,-690 435,690, body extent -433,-690 433,690, height 1305
IPAK [mm] "IPAK"
  rrect50% 1.75x2 hole 1.25: 1(-2.28,0)
  oval 1.75x2 hole 1.25: 2(0,0) 3(2.28,0)
  silkscreen extent -3.4,-1.1 3.4,1.3, body extent -3.25,-0.99 3.25,1.31, height 9.66
KEYSTONE5000 [mil] "For Keystone 500x miniature loop terminals"
  round 80 hole 40: 1(0,0)
  silkscreen extent -58,-58 58,58, body extent -49,-49 49,49, height 182
Keystone5000 [mil] "For Keystone 500x miniature loop terminals"
  round 80 hole 40: 1(0,0)
  silkscreen extent -58,-58 58,58, body extent -49,-49 49,49, height 182
KEYSTONE5001 [mil] "For Keystone 500x miniature loop terminals"
  round 80 hole 40: 1(0,0)
  silkscreen extent -58,-58 58,58, body extent -49,-49 49,49, height 182
Keystone5001 [mil] "For Keystone 500x miniature loop terminals"
  round 80 hole 40: 1(0,0)
  silkscreen extent -58,-58 58,58, body extent -49,-49 49,49, height 182
Keystone5002 [mil] "For Keystone 500x miniature loop terminals"
  round 80 hole 40: 1(0,0)
  silkscreen extent -58,-58 58,58, body extent -49,-49 49,49, height 182
Keystone_1902C [mil] "Hex Standoff, 4-40 threaded, nylon"
  round 1 on Mech4: 0(0,0)
  body extent -145,-126 146,126, height 501
Label_1250x250 [mil] "Thermal Transfer Labels"
  round 1 on Mech13: 0(0,0)
  silkscreen extent -625,-125 625,125, body extent -625,-125 625,125, height 1
"LG L29K_GREEN" [mm] "OSRAM"
  rect 0.8x0.8 smd paste-0.4: 1(-0.75,0) 2(0.75,0)
  silkscreen extent -0.1,-0.5 1.45,0.5, body extent -0.9,-0.45 0.9,0.45, height 0.67
LQH43M [mm] "SMD, 2-Leads, Body 4.5x3.2mm"
  rect 1.5x3 smd: 1(-1.5,0) 2(1.5,0)
  Layer 1 - Top Layer region: 3.75,-0.75 2.25,-0.75 2.25,0.75 3.75,0.75
  Layer 1 - Top Layer region: -3.75,0.75 -2.25,0.75 -2.25,-0.75 -3.75,-0.75
  silkscreen extent -0.4,-1.6 0.4,1.6, body extent -2.25,-1.6 2.25,1.6, height 2.6
Mill-Max_0312-0-15-15-34-27-10-0 [mm] "Pin Receptacle, .032-.046\" .075\" Dia, Gold, TH"
  round 2.45 hole 1.905: 1(0,0)
  silkscreen extent -1.52,-1.52 1.52,1.52, body extent -1.15,-1.15 1.16,1.15, height 0.46
Molex_0448120024 [mm] "Receptacle, 2.54mm, 6x1, TH"
  round 1.55 hole 1.02: 1(-6.35,-1.905) 2(-3.81,-1.905) 2(-3.81,1.905) 3(-1.27,-1.905) 3(-1.27,1.905) 4(1.27,-1.905) 4(1.27,1.905) 5(3.81,-1.905) 5(3.81,1.905) 6(6.35,-1.905) 6(6.35,1.905)
  rect 1.55x1.55 hole 1.02: 1(-6.35,1.905)
  silkscreen extent -8.2,-4.09 8.08,3.4, body extent -7.92,-4.09 8.08,3.4, height 4.5
MPK_1800x950 [mm] "TH, 2-Leads, Body 18x9.5mm, Lead Spacing 15mm"
  round 1.55 hole 1.05: 1(-7.5,0) 2(7.5,0)
  silkscreen extent -9,-4.75 9,4.75, body extent -9,-4.75 9,4.75, height 14
MUA08A_N [mm] "TSOP, 8-Leads, Body 3x3mm, Pitch 0.65mm, IPC Medium Density"
  oval 1.7x0.45 smd: 1(-2.1,0.975) 2(-2.1,0.325) 3(-2.1,-0.325) 4(-2.1,-0.975) 5(2.1,-0.975) 6(2.1,-0.325) 7(2.1,0.325) 8(2.1,0.975)
  silkscreen extent -2.22,-1.55 0.85,1.88, body extent -1.6,-1.6 1.6,1.6, height 1.09
Net-Tie_50milWide_30milLong [mil] "50mil net tie, no solder mask opening, no solder paste"
  rect 30x50 on Mid4 paste-20 mask-20: 1(-15,0) 2(15,0)
"NY PMS 440 0025 PH" [mm] "4-40 nylon screw and mounting hole"
  round 8 hole 3.2: 1(0,0)
  body extent -3.3,-3.3 3.3,3.3, height 2.69
Pb-Free_Overlay_Small [mil]
  silkscreen extent -46,-46 46,46
Relay_G5Q-1A4 [mm] "TH, 4-Leads, Body 20x10mm"
  rect 1.8x1.8 hole 1.3: 1(-3.81,8.97)
  round 1.8 hole 1.3: 2(-3.81,-1.19) 3(-3.81,-8.81) 5(3.81,8.97)
  silkscreen extent -5.5,-10.15 5.15,10.15, body extent -5.15,-10.15 5.15,10.15, height 16.21
RGT0016C [mm] "QFN, 16-Leads, Body 3x3mm, Pitch 0.5mm, Thermal Pad 1.7x1.7mm, TI Recommended"
  rrect40% 0.6x0.25 smd: 1(-1.4,0.75) 2(-1.4,0.25) 3(-1.4,-0.25) 4(-1.4,-0.75) 9(1.4,-0.75) 10(1.4,-0.25) 11(1.4,0.25) 12(1.4,0.75)
  rrect40% 0.25x0.6 smd: 5(-0.75,-1.4) 6(-0.25,-1.4) 7(0.25,-1.4) 8(0.75,-1.4) 13(0.75,1.4) 14(0.25,1.4) 15(-0.25,1.4) 16(-0.75,1.4)
  rrect6% 1.55x1.55 on Bottom Paste: 17(0,0)
  rrect6% 1.7x1.7 smd paste-0.85: 17(0,0)
  silkscreen extent -1.72,-1.73 1.72,1.73, body extent -1.57,-1.57 1.58,1.58, height 1.01
RHA0040B [mm] "QFN, 40-Leads, Body 6x6mm, Pitch 0.5mm, Thermal Pad 4.15 x 4.15mm, TI Recommended"
  oval 0.6x0.23 smd mask+0.07: 1(-2.9,2.25) 2(-2.9,1.75) 3(-2.9,1.25) 4(-2.9,0.75) 5(-2.9,0.25) 6(-2.9,-0.25) 7(-2.9,-0.75) 8(-2.9,-1.25) 9(-2.9,-1.75) 10(-2.9,-2.25) 21(2.9,-2.25) 22(2.9,-1.75) 23(2.9,-1.25) 24(2.9,-0.75) 25(2.9,-0.25) 26(2.9,0.25) 27(2.9,0.75) 28(2.9,1.25) 29(2.9,1.75) 30(2.9,2.25)
  oval 0.23x0.6 smd mask+0.07: 11(-2.25,-2.9) 12(-1.75,-2.9) 13(-1.25,-2.9) 14(-0.75,-2.9) 15(-0.25,-2.9) 16(0.25,-2.9) 17(0.75,-2.9) 18(1.25,-2.9) 19(1.75,-2.9) 20(2.25,-2.9) 31(2.25,2.9) 32(1.75,2.9) 33(1.25,2.9) 34(0.75,2.9) 35(0.25,2.9) 36(-0.25,2.9) 37(-0.75,2.9) 38(-1.25,2.9) 39(-1.75,2.9) 40(-2.25,2.9)
  rect 4.15x4.15 smd paste-2.1: 41(0,0)
  silkscreen extent -3.22,-3.22 3.22,3.22, body extent -3.08,-3.08 3.08,3.08, height 1.01
Samtec_BNC5-J-P-GN-ST-TH2D [mm] "50 OHM BNC ELEVATED STRAIGHT JACK, TH"
  rect 1.55x1.55 hole 1.05: 1(0,0)
  round 2.35 hole 1.85: 2(-3.43,3.43) 3(-3.43,-3.43) 4(3.43,-3.43)
  silkscreen extent -5.53,-5.46 5.53,5.46, body extent -5.53,-5.46 5.54,5.46, height 19.69
Samtec_PESC-02-12-02-01-x-RA-LC [mm] "Connector, 4x3, 4 Power Group, R/A, TH"
  rect 1.55x1.55 hole 1.02: 1(-2.54,-4.293)
  round 1.55 hole 1.02: 2(-2.54,-6.833) 3(-2.54,-9.373) 4(-2.54,-11.913) 5(0,-4.293) 6(0,-6.833) 7(0,-9.373) 8(0,-11.913) 9(2.54,-4.293) 10(2.54,-6.833) 11(2.54,-9.373) 12(2.54,-11.913)
  round 0 hole 2.49 unplated: MH1(-22.225,-6.96) MH2(22.225,-6.96)
  round 1.85 hole 1.32: P1(-15.875,-6.96) P1(-15.875,-4.42) P1(-15.875,-12.04) P1(-15.875,-9.5) P1(-13.335,-6.96) P1(-13.335,-4.42) P1(-13.335,-12.04) P1(-13.335,-9.5) P2(-9.525,-6.96) P2(-9.525,-9.5) P2(-9.525,-4.42) P2(-9.525,-12.04) P2(-6.985,-9.5) P2(-6.985,-6.96) P2(-6.985,-4.42) P2(-6.985,-12.04) P3(6.985,-9.5) P3(6.985,-6.96) P3(6.985,-4.42) P3(6.985,-12.04) P3(9.525,-9.5) P3(9.525,-6.96) P3(9.525,-4.42) P3(9.525,-12.04) P4(13.335,-6.96) P4(13.335,-4.42) P4(13.335,-12.04) P4(13.335,-9.5) P4(15.875,-6.96) P4(15.875,-4.42) P4(15.875,-12.04) P4(15.875,-9.5)
  silkscreen extent -26.7,-12.5 26.03,-0.3, body extent -26.04,-12.5 26.03,12.7, height 11.25
SDR0403 [mm] "BOURNS"
  rect 1.8x4.5 smd: 1(-1.65,0) 2(1.65,0)
  body extent -2.4,-2.4 2.4,2.4, height 3.3
SMA [mm] "Molded Diode, 2-Leads, Body 4.3x2.6mm, IPC Medium Density, based on OnSemi component dimensions and land pattern"
  rect 2x2 smd: 1(-2,0) 2(2,0)
  silkscreen extent -3.66,-1.57 2.79,1.57, body extent -2.6,-1.3 2.6,1.3, height 2.42
SOD-123 [mm] "On Semi recommended land pattern"
  rect 0.915x1.22 smd: 1(-1.637,0) 2(1.637,0)
  silkscreen extent -2.74,-1.17 2.03,1.17, body extent -1.93,-0.9 1.93,0.9, height 1.35
SOIC-16 [mm] "SOIC, 16-Leads, Body 10.3x7.5mm, Pitch 1.27mm"
  rect 2.25x0.65 smd: 1(-4.75,4.445) 2(-4.75,3.175) 3(-4.75,1.905) 4(-4.75,0.635) 5(-4.75,-0.635) 6(-4.75,-1.905) 7(-4.75,-3.175) 8(-4.75,-4.445) 9(4.75,-4.445) 10(4.75,-3.175) 11(4.75,-1.905) 12(4.75,-0.635) 13(4.75,0.635) 14(4.75,1.905) 15(4.75,3.175) 16(4.75,4.445)
  silkscreen extent -4.87,-5.25 3.8,5.44, body extent -3.8,-5.25 3.8,5.25, height 2.65
SOT-23 [mm] "SOT23, 3-Leads, Body 2.9x1.3mm, Pitch 0.95mm, Lead Span 2.5mm, IPC Medium Density"
  rrect50% 1x0.6 smd: 1(-1.2,0.95) 2(-1.2,-0.95) 3(1.2,0)
  silkscreen extent -1.62,-1.5 0.7,1.5, body extent -1.16,-1.45 1.21,1.45, height 1
SW_SKRKAEE010 [mm] "Alps recommended land pattern"
  rect 0.8x2 smd: 1(-2.1,0) 2(2.1,0)
  silkscreen extent -1.9,-1.44 1.92,1.44, body extent -2.4,-1.45 2.4,1.45, height 1.96
TDK_B751 [mm] "TH, 2-Leads, Dia 12.5mm, Pin Spacing 5mm"
  round 1.35 hole 0.85: 1(0,2.5) 2(0,-2.5)
  silkscreen extent -3.5,-6.25 3.5,6.25, body extent -3.48,-6.2 3.48,6.25, height 16.49
TEC_282841-2 [mm] "TE Connectivity"
  rect 2.15x2.15 hole 1.4: 1(-2.54,0)
  round 2.15 hole 1.4: 2(2.54,0)
  silkscreen extent -5.9,-4.52 5.55,4.47, body extent -5.08,-4.52 5.58,4.48, height 15.2
TO-247 [mil] "Standard TO-247"
  rect 95x95 hole 62: 1(-215,0)
  round 95 / inner round 74.8 / far side round 96 hole 62: 2(0,0) 3(215,0)
  silkscreen extent -318,-124 318,81, body extent -318,-124 318,81, height 1007
TSW-103-07-G-S [mm] "Samtec 100mil, 1x3, 230 mil above insulator"
  rect 1.65x1.65 hole 1.016: 1(-2.54,0)
  round 1.65 hole 1.016: 2(0,0) 3(2.54,0)
  silkscreen extent -3.81,-1.27 3.81,1.65, body extent -3.81,-1.27 3.81,1.27, height 8.38
TSW-104-07-G-D [mm] "Samtec 100mil, 2x4, 230 mil above insulator"
  rrect6% 1.65x1.65 hole 1.016: 1(-3.81,-1.27)
  round 1.65 hole 1.016: 2(-3.81,1.27) 3(-1.27,-1.27) 4(-1.27,1.27) 5(1.27,-1.27) 6(1.27,1.27) 7(3.81,-1.27) 8(3.81,1.27)
  silkscreen extent -6.1,-2.54 5.08,2.54, body extent -5.08,-2.54 5.08,2.54, height 8.38
TSW-105-07-G-D [mm] "Samtec 100mil, 2x5, 230 mil above insulator"
  rrect6% 1.65x1.65 hole 1.016: 1(-5.08,-1.27)
  round 1.65 hole 1.016: 2(-5.08,1.27) 3(-2.54,-1.27) 4(-2.54,1.27) 5(0,-1.27) 6(0,1.27) 7(2.54,-1.27) 8(2.54,1.27) 9(5.08,-1.27) 10(5.08,1.27)
  silkscreen extent -7.38,-2.54 6.35,2.54, body extent -6.35,-2.54 6.35,2.54, height 8.38
Wurth_750315894 [mm] "TH, 10-Leads, Body 14.73x14.73mm, Pitch 2.5mm"
  rect 1.7x1.7 hole 1.2: 1(-4.255,5)
  round 1.7 hole 1.2: 2(-4.255,2.5) 3(-4.255,0) 4(-4.255,-2.5) 5(-4.255,-5) 6(4.255,-5) 7(4.255,-2.5) 8(4.255,0) 9(4.255,2.5) 10(4.255,5)
  silkscreen extent -8,-7.36 7.36,7.36, body extent -7.36,-7.36 7.37,7.37, height 15.24
ZL_1000x1250 [mm] "TH, 2-Leads, Body 10x12.5mm, Pin Spacing 5mm"
  rect 1.35x1.35 hole 0.85: 1(-2.5,0)
  round 1.35 hole 0.85: 2(2.5,0)
  silkscreen extent -5.25,-5.25 5.25,5.25, body extent -5.25,-5.25 5.25,5.25, height 14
